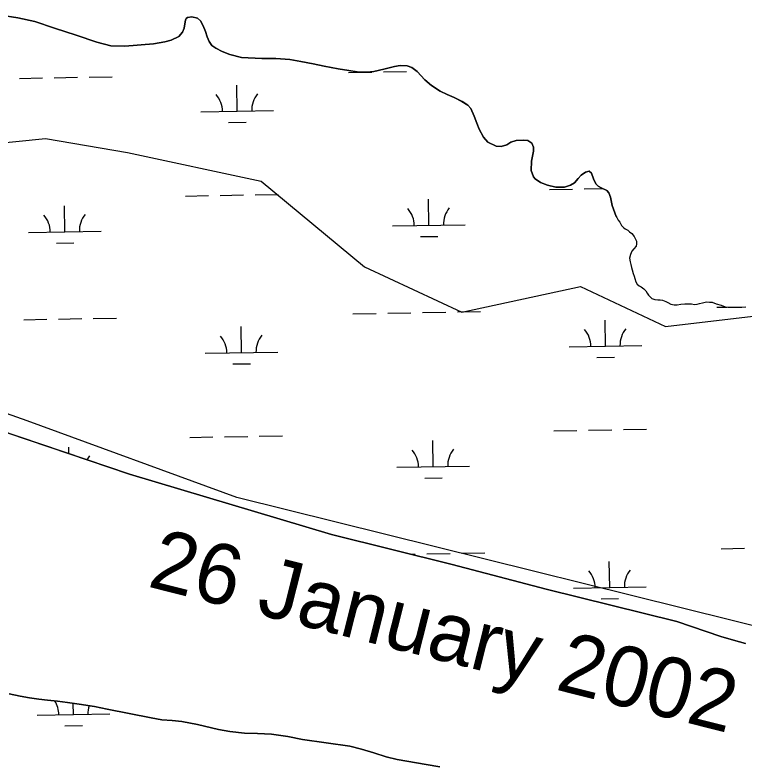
# Model space of a CAD drawing. Extents: x 3914892 to 3953151, y 242587 to 268572.
# Drawn here: x 3947793 to 3948799, y 254679 to 255715 of the extents above; entities that cross this region are included whole.
import ezdxf

# ---------------------------------------------------------------- set-up
doc = ezdxf.new("R2010")
doc.units = 0
for name, color, linetype in [('V-RIVR-IDEN', 7, 'Continuous'), ('V-SITE-VEGE', 7, 'Continuous'), ('V-TOPO-SHOR', 7, 'Continuous'), ('V-WETL-SWMP', 7, 'Continuous')]:
    doc.layers.add(name, color=color, linetype=linetype)

msp = doc.modelspace()

# ---------------------------------------------------------------- linework, layer by layer
at = {"layer": 'V-SITE-VEGE'}
for points in [[(3947679.8, 255529.4), (3947834.8, 255545.1), (3947947.9, 255525.5), (3948132.3, 255486.2), (3948274.7, 255368.3), (3948408.8, 255305.4), (3948572.2, 255340.8), (3948689.5, 255285.8), (3948857.1, 255305.4), (3948928.4, 255325.1), (3948999.6, 255356.5), (3949054.1, 255376.1), (3949066.6, 255376.1), (3949129.5, 255395.8), (3949163, 255340.8), (3949204.9, 255293.6), (3949288.7, 255258.3), (3949318, 255250.4), (3949401.8, 255297.5), (3949506.6, 255289.7), (3949552.7, 255266.1)], [(3949615.5, 254731.7), (3949368.3, 254751.3), (3948987, 254829.9), (3948098.8, 255050), (3947809.7, 255156.1), (3947520.6, 255258.3)]]:
    msp.add_lwpolyline(points, dxfattribs=at)
at = {"layer": 'V-TOPO-SHOR'}
for points in [[(3948621.7, 255437.5), (3948616.2, 255452.6), (3948613.6, 255464.2), (3948611.5, 255470), (3948608.5, 255473.4), (3948601, 255476.9), (3948596.7, 255479.1), (3948593.5, 255482.4), (3948590.4, 255489.4), (3948587.6, 255497.4), (3948584.4, 255499.8), (3948579.2, 255498.7), (3948573.4, 255494.6), (3948569.1, 255489.7), (3948563.9, 255484), (3948558.6, 255480.7), (3948550.2, 255478), (3948538.3, 255478), (3948526.8, 255480.8), (3948517.1, 255484.5), (3948509.8, 255489.4), (3948507.4, 255492.2), (3948504.6, 255501), (3948504.9, 255513.8), (3948507.7, 255527.3), (3948507.4, 255532.9), (3948505.5, 255538.7), (3948499.6, 255542.1), (3948493.2, 255542.8), (3948483.5, 255542.4), (3948476.4, 255539.9), (3948470.8, 255536.4), (3948463, 255534.1), (3948456, 255534.4), (3948444.6, 255539.8), (3948438.5, 255547), (3948432.9, 255557.7), (3948429.4, 255566.1), (3948426, 255575.7), (3948421.2, 255586.3), (3948417.2, 255590.8), (3948409.1, 255595.9), (3948398.1, 255601.4), (3948388.8, 255605.4), (3948378.9, 255610.1), (3948366.8, 255618), (3948358, 255625.9), (3948347.2, 255637.4), (3948339.7, 255642.9), (3948333.4, 255645), (3948323.8, 255645.4), (3948315.8, 255644.3), (3948301.4, 255640.3), (3948287.6, 255637.1), (3948277.9, 255636.5), (3948264.5, 255636.9), (3948252.8, 255638.5), (3948238.1, 255640.9), (3948219.2, 255644.5), (3948203.9, 255647.7), (3948186.9, 255651.2), (3948171.8, 255654), (3948152.3, 255655.1), (3948132.9, 255655.4), (3948105.1, 255656.4), (3948089.2, 255660.6), (3948078.5, 255665), (3948069.8, 255669.5), (3948064.3, 255673.3), (3948060.4, 255678.6), (3948057.5, 255685.2), (3948055.2, 255692.2), (3948052.1, 255700), (3948048.4, 255707.2), (3948044.5, 255710.7), (3948036.8, 255712.8), (3948030.8, 255711.5), (3948028.6, 255710.3), (3948027.9, 255708.1), (3948027.1, 255703), (3948025.8, 255697.2), (3948023.9, 255691.5), (3948018.6, 255685.6), (3948008.2, 255680.5), (3947999.2, 255678.1), (3947983.6, 255675.5), (3947944.1, 255672.3), (3947924.8, 255672.6), (3947905.8, 255677.9), (3947877, 255687.5), (3947847.3, 255696.9), (3947820.3, 255706.1), (3947796.9, 255711.2), (3947773.2, 255715.1)], [(3948621.7, 255437.5), (3948622.3, 255436.1), (3948624.5, 255432.3), (3948626.5, 255429.6), (3948629, 255425.1), (3948631.6, 255422.3), (3948634.1, 255420.4), (3948637.6, 255418.4), (3948640.1, 255416.3), (3948643, 255413.9), (3948646.3, 255409.9), (3948647.9, 255407.1), (3948649.7, 255403.3), (3948649.8, 255400), (3948648.9, 255396.8), (3948646.1, 255392.9), (3948643.3, 255389.6), (3948641.1, 255385.3), (3948640, 255379.9), (3948640.7, 255374.8), (3948641.7, 255371.4), (3948642.9, 255367.2), (3948643.8, 255363.9), (3948645, 255359), (3948646.2, 255355.2), (3948647.2, 255351.9), (3948648.8, 255347.6), (3948650.6, 255344), (3948653.1, 255342.1), (3948655.9, 255340.6), (3948659.5, 255337.8), (3948662.5, 255334.8), (3948664.2, 255332), (3948666, 255328.9), (3948668.2, 255326.7), (3948670.7, 255324.6), (3948674.9, 255323), (3948679, 255322.5), (3948682, 255322.7), (3948685.5, 255322.2), (3948689.9, 255320.4), (3948692.8, 255318.9), (3948696.9, 255316.7), (3948701.5, 255315.6), (3948705.5, 255315.7), (3948710.6, 255316.8), (3948716.4, 255317.1), (3948721.7, 255317.3), (3948725.2, 255317), (3948729.6, 255316.3), (3948733.2, 255316.6), (3948736.6, 255317.6), (3948740.5, 255318.6), (3948746, 255319.7), (3948750.2, 255319.6), (3948754, 255319.3), (3948759.6, 255317.3), (3948766.2, 255315.1), (3948771.8, 255312.9), (3948776, 255312.4), (3948781.3, 255312.3), (3948785, 255312.4), (3948790.3, 255312.5), (3948794.7, 255312.6), (3948800.5, 255312.9)], [(3947054, 255408.5), (3947327.2, 255301.4), (3947494.9, 255241.7), (3947755, 255148.5), (3947950.8, 255082.4), (3948229.1, 254999.4), (3948395.6, 254958.1), (3948525.2, 254923.7), (3948705.2, 254879.3)], [(3948705.2, 254879.3), (3948765.8, 254858.5), (3948783.4, 254853.7), (3948799.8, 254849)], [(3948073.2, 254730.3), (3948044.6, 254737.3), (3948022.7, 254741.5), (3948009.5, 254742.7), (3947995.1, 254743.7), (3947980.7, 254746.6), (3947919.9, 254758.7), (3947902.3, 254762.1), (3947881.2, 254765.4), (3947865.3, 254767.7), (3947851.6, 254769.5), (3947837.7, 254770.8), (3947825.9, 254772.5), (3947812.8, 254774), (3947799.8, 254776.4), (3947784.7, 254779.6)], [(3948378.6, 254678.9), (3948359.4, 254682.5), (3948319.5, 254689.1), (3948304.7, 254693), (3948287.3, 254698.3), (3948270.6, 254703.4), (3948254.5, 254707.5), (3948189.2, 254716.7), (3948168.9, 254720.7), (3948146.5, 254724.1), (3948127.2, 254725.2), (3948109.4, 254725.3), (3948088.8, 254727.8), (3948073.2, 254730.3)]]:
    msp.add_lwpolyline(points, dxfattribs=at)
at = {"layer": 'V-WETL-SWMP'}
for p, q in [((3947773.1, 255715.1), (3947796.9, 255711.2)), ((3947796.9, 255711.2), (3947820.3, 255706.1)), ((3948028.6, 255710.3), (3948030.8, 255711.5)), ((3948030.8, 255711.5), (3948036.8, 255712.8)), ((3948036.8, 255712.8), (3948044.5, 255710.7)), ((3948044.5, 255710.7), (3948048.4, 255707.2)), ((3947820.3, 255706.1), (3947847.3, 255696.9)), ((3948025.8, 255697.2), (3948027.1, 255703)), ((3948027.1, 255703), (3948027.9, 255708.1)), ((3948027.9, 255708.1), (3948028.6, 255710.3)), ((3948048.4, 255707.2), (3948052.1, 255700)), ((3947847.3, 255696.9), (3947877, 255687.5)), ((3948018.6, 255685.6), (3948023.9, 255691.5)), ((3948023.9, 255691.5), (3948025.8, 255697.2)), ((3948052.1, 255700), (3948055.2, 255692.2)), ((3948055.2, 255692.2), (3948057.5, 255685.2)), ((3947877, 255687.5), (3947905.8, 255677.9)), ((3947999.2, 255678.1), (3948008.2, 255680.5)), ((3948008.2, 255680.5), (3948018.6, 255685.6)), ((3948057.5, 255685.2), (3948060.4, 255678.6)), ((3947905.8, 255677.9), (3947924.8, 255672.6)), ((3947924.8, 255672.6), (3947944.1, 255672.3)), ((3947944.1, 255672.3), (3947983.6, 255675.5)), ((3947983.6, 255675.5), (3947999.2, 255678.1)), ((3948060.4, 255678.6), (3948064.3, 255673.3)), ((3948064.3, 255673.3), (3948069.8, 255669.5)), ((3948069.8, 255669.5), (3948078.5, 255665)), ((3948078.5, 255665), (3948089.2, 255660.6)), ((3948089.2, 255660.6), (3948105.1, 255656.4)), ((3948105.1, 255656.4), (3948132.9, 255655.4)), ((3948132.9, 255655.4), (3948152.3, 255655.1)), ((3948152.3, 255655.1), (3948171.8, 255654)), ((3948171.8, 255654), (3948186.9, 255651.2)), ((3948186.9, 255651.2), (3948203.9, 255647.7)), ((3948203.9, 255647.7), (3948219.2, 255644.5)), ((3948219.2, 255644.5), (3948238.1, 255640.9)), ((3948238.1, 255640.9), (3948252.8, 255638.5)), ((3948252.8, 255638.5), (3948264.5, 255636.9)), ((3948287.6, 255637.1), (3948301.4, 255640.3)), ((3948301.4, 255640.3), (3948315.8, 255644.3)), ((3948315.8, 255644.3), (3948323.8, 255645.4)), ((3948323.8, 255645.4), (3948333.4, 255645)), ((3948333.4, 255645), (3948339.7, 255642.9)), ((3948339.7, 255642.9), (3948347.2, 255637.4)), ((3947798.9, 255627.8), (3947830.9, 255628.4)), ((3947846.9, 255628.7), (3947878.9, 255629.3)), ((3947894.9, 255629.6), (3947926.8, 255630.1)), ((3948252.7, 255636), (3948284.7, 255636.5)), ((3948264.5, 255636.9), (3948277.9, 255636.5)), ((3948277.9, 255636.5), (3948287.6, 255637.1)), ((3948300.7, 255636.8), (3948332.7, 255637.4)), ((3948347.2, 255637.4), (3948358, 255625.9)), ((3948099, 255582.5), (3948098.4, 255618.5)), ((3948358, 255625.9), (3948366.8, 255618)), ((3948366.8, 255618), (3948378.9, 255610.1)), ((3948378.9, 255610.1), (3948388.8, 255605.4)), ((3948388.8, 255605.4), (3948398.1, 255601.4)), ((3948398.1, 255601.4), (3948409, 255595.9)), ((3948409, 255595.9), (3948417.2, 255590.8)), ((3948417.2, 255590.8), (3948421.2, 255586.3)), ((3948421.2, 255586.3), (3948426, 255575.7)), ((3948049.1, 255581.6), (3948149, 255583.4)), ((3948087.3, 255566.8), (3948111.3, 255567.3)), ((3948426, 255575.7), (3948429.4, 255566.1)), ((3948429.4, 255566.1), (3948432.9, 255557.7)), ((3948432.9, 255557.7), (3948438.5, 255547)), ((3948438.5, 255547), (3948444.6, 255539.8)), ((3948444.6, 255539.8), (3948456, 255534.4)), ((3948456, 255534.4), (3948463, 255534.1)), ((3948463, 255534.1), (3948470.8, 255536.4)), ((3948470.8, 255536.4), (3948476.4, 255539.9)), ((3948476.4, 255539.9), (3948483.5, 255542.4)), ((3948483.5, 255542.4), (3948493.2, 255542.8)), ((3948493.2, 255542.8), (3948499.6, 255542.1)), ((3948499.6, 255542.1), (3948505.5, 255538.7)), ((3948505.5, 255538.7), (3948507.4, 255532.9)), ((3948507.7, 255527.3), (3948504.9, 255513.8)), ((3948507.4, 255532.9), (3948507.7, 255527.3)), ((3948504.9, 255513.8), (3948504.6, 255501)), ((3948504.6, 255501), (3948507.4, 255492.2)), ((3948569.1, 255489.7), (3948573.4, 255494.6)), ((3948573.4, 255494.6), (3948579.2, 255498.7)), ((3948579.2, 255498.7), (3948584.4, 255499.8)), ((3948584.4, 255499.8), (3948587.6, 255497.4)), ((3948587.6, 255497.4), (3948590.4, 255489.4)), ((3948507.4, 255492.2), (3948509.8, 255489.4)), ((3948509.8, 255489.4), (3948517.1, 255484.5)), ((3948517.1, 255484.5), (3948526.8, 255480.8)), ((3948558.6, 255480.7), (3948563.9, 255484)), ((3948563.9, 255484), (3948569.1, 255489.7)), ((3948590.4, 255489.4), (3948593.5, 255482.4)), ((3948526.8, 255480.8), (3948538.3, 255478)), ((3948529.5, 255474.7), (3948561.5, 255475.3)), ((3948538.3, 255478), (3948550.2, 255478)), ((3948550.2, 255478), (3948558.6, 255480.7)), ((3948577.5, 255475.6), (3948602.9, 255476)), ((3948593.5, 255482.4), (3948596.7, 255479.1)), ((3948596.7, 255479.1), (3948601, 255476.9)), ((3948601, 255476.9), (3948608.5, 255473.4)), ((3948608.5, 255473.4), (3948611.5, 255470)), ((3948027.7, 255465.7), (3948059.7, 255466.3)), ((3948075.7, 255466.6), (3948107.7, 255467.2)), ((3948123.7, 255467.5), (3948155.7, 255468)), ((3948611.5, 255470), (3948613.6, 255464.2)), ((3948613.6, 255464.2), (3948616.2, 255452.6)), ((3947861.5, 255416.3), (3947860.9, 255452.3)), ((3948363.3, 255425.3), (3948362.7, 255461.3)), ((3948616.2, 255452.6), (3948621.7, 255437.5)), ((3948621.7, 255437.5), (3948622.3, 255436.1)), ((3948622.3, 255436.1), (3948624.5, 255432.3)), ((3948624.5, 255432.3), (3948626.5, 255429.6)), ((3948313.3, 255424.4), (3948413.3, 255426.2)), ((3948626.5, 255429.6), (3948629, 255425.1)), ((3948629, 255425.1), (3948631.6, 255422.3)), ((3948631.6, 255422.3), (3948634.1, 255420.4)), ((3948634.1, 255420.4), (3948637.6, 255418.4)), ((3947811.5, 255415.4), (3947911.5, 255417.2)), ((3948351.6, 255409.7), (3948375.6, 255410.1)), ((3948637.6, 255418.4), (3948640.1, 255416.3)), ((3948640.1, 255416.3), (3948643, 255413.9)), ((3948643, 255413.9), (3948646.3, 255409.9)), ((3947849.8, 255400.7), (3947873.8, 255401.1)), ((3948646.3, 255409.9), (3948647.9, 255407.1)), ((3948647.9, 255407.1), (3948649.7, 255403.3)), ((3948649.8, 255400), (3948648.9, 255396.8)), ((3948649.7, 255403.3), (3948649.8, 255400)), ((3948643.3, 255389.6), (3948641.1, 255385.3)), ((3948646.1, 255392.9), (3948643.3, 255389.6)), ((3948648.9, 255396.8), (3948646.1, 255392.9)), ((3948641.1, 255385.3), (3948640, 255379.9)), ((3948640, 255379.9), (3948640.7, 255374.8)), ((3948640.7, 255374.8), (3948641.7, 255371.4)), ((3948641.7, 255371.4), (3948642.9, 255367.2)), ((3948642.9, 255367.2), (3948643.8, 255363.9)), ((3948643.8, 255363.9), (3948645, 255359)), ((3948645, 255359), (3948646.2, 255355.2)), ((3948646.2, 255355.2), (3948647.2, 255351.9)), ((3948647.2, 255351.9), (3948648.8, 255347.6)), ((3948648.8, 255347.6), (3948650.6, 255344)), ((3948650.6, 255344), (3948653.1, 255342.1)), ((3948653.1, 255342.1), (3948655.9, 255340.6)), ((3948655.9, 255340.6), (3948659.5, 255337.8)), ((3948659.5, 255337.8), (3948662.5, 255334.8)), ((3948662.5, 255334.8), (3948664.2, 255332)), ((3948664.2, 255332), (3948666, 255328.9)), ((3948666, 255328.9), (3948668.2, 255326.7)), ((3948668.2, 255326.7), (3948670.7, 255324.6)), ((3948670.7, 255324.6), (3948674.9, 255323)), ((3948674.9, 255323), (3948679, 255322.5)), ((3948679, 255322.5), (3948682, 255322.7)), ((3948682, 255322.7), (3948685.5, 255322.2)), ((3948685.5, 255322.2), (3948689.9, 255320.4)), ((3948689.9, 255320.4), (3948692.8, 255318.9)), ((3948692.8, 255318.9), (3948696.9, 255316.7)), ((3948705.5, 255315.7), (3948710.6, 255316.8)), ((3948710.6, 255316.8), (3948716.4, 255317.1)), ((3948716.4, 255317.1), (3948721.7, 255317.3)), ((3948721.7, 255317.3), (3948725.2, 255317)), ((3948725.2, 255317), (3948729.6, 255316.3)), ((3948733.2, 255316.6), (3948736.6, 255317.6)), ((3948736.6, 255317.6), (3948740.5, 255318.6)), ((3948740.5, 255318.6), (3948746, 255319.7)), ((3948746, 255319.7), (3948750.2, 255319.6)), ((3948750.2, 255319.6), (3948754, 255319.3)), ((3948754, 255319.3), (3948759.6, 255317.3)), ((3948759.6, 255317.3), (3948766.2, 255315.1)), ((3948402.6, 255305.9), (3948434.6, 255306.5)), ((3948696.9, 255316.7), (3948701.5, 255315.6)), ((3948701.5, 255315.6), (3948705.5, 255315.7)), ((3948729.6, 255316.3), (3948733.2, 255316.6)), ((3948760.5, 255312.3), (3948774.6, 255312.6)), ((3948766.2, 255315.1), (3948771.8, 255312.9)), ((3948771.8, 255312.9), (3948776, 255312.4)), ((3948776, 255312.4), (3948781.3, 255312.3)), ((3948781.3, 255312.3), (3948785, 255312.4)), ((3948785, 255312.4), (3948790.3, 255312.5)), ((3948790.3, 255312.5), (3948794.7, 255312.6)), ((3948794.7, 255312.6), (3948800.5, 255312.9)), ((3947852.8, 255296.1), (3947884.8, 255296.7)), ((3947900.8, 255296.9), (3947932.8, 255297.5)), ((3948258.7, 255303.3), (3948290.6, 255303.9)), ((3948306.6, 255304.2), (3948338.6, 255304.8)), ((3948354.6, 255305.1), (3948386.6, 255305.6)), ((3947804.8, 255295.2), (3947836.8, 255295.8)), ((3948105, 255249.8), (3948104.4, 255285.8)), ((3948606.8, 255258.8), (3948606.2, 255294.8)), ((3948556.8, 255257.9), (3948656.8, 255259.7)), ((3948055, 255248.9), (3948155, 255250.7)), ((3948093.3, 255234.2), (3948117.3, 255234.6)), ((3948595.1, 255243.2), (3948619.1, 255243.6)), ((3947950.8, 255082.4), (3947755, 255148.5)), ((3948535.5, 255142.1), (3948567.5, 255142.7)), ((3948583.5, 255143), (3948615.5, 255143.5)), ((3948631.5, 255143.8), (3948663.5, 255144.4)), ((3948033.7, 255133.1), (3948065.7, 255133.7)), ((3948081.7, 255134), (3948113.6, 255134.5)), ((3948129.6, 255134.8), (3948161.6, 255135.4)), ((3948369.3, 255092.7), (3948368.6, 255128.7)), ((3947867, 255110.7), (3947866.8, 255119.7)), ((3948319.3, 255091.8), (3948419.3, 255093.6)), ((3948229.1, 254999.4), (3947950.8, 255082.4)), ((3948357.6, 255077), (3948381.6, 255077.5)), ((3948395.6, 254958.1), (3948229.1, 254999.4)), ((3948766.4, 254979.7), (3948798.4, 254980.3)), ((3948339.4, 254972.1), (3948344.6, 254972.2)), ((3948360.6, 254972.4), (3948392.6, 254973)), ((3948408.6, 254973.3), (3948440.6, 254973.9)), ((3948525.2, 254923.7), (3948395.6, 254958.1)), ((3948612.8, 254926.2), (3948612.1, 254962.2)), ((3948705.2, 254879.3), (3948525.2, 254923.7)), ((3948562.8, 254925.3), (3948662.8, 254927.1)), ((3948601.1, 254910.6), (3948625, 254911)), ((3948765.8, 254858.5), (3948705.2, 254879.3)), ((3948783.4, 254853.7), (3948765.8, 254858.5)), ((3948799.8, 254849), (3948783.4, 254853.7)), ((3947784.7, 254779.6), (3947799.8, 254776.4)), ((3947799.8, 254776.4), (3947812.8, 254774)), ((3947812.8, 254774), (3947825.9, 254772.5)), ((3947825.9, 254772.5), (3947837.7, 254770.8)), ((3947837.7, 254770.8), (3947851.6, 254769.5)), ((3947851.6, 254769.5), (3947865.3, 254767.7)), ((3947865.3, 254767.7), (3947881.2, 254765.4)), ((3947873.4, 254751.1), (3947873.1, 254766.5)), ((3947881.2, 254765.4), (3947902.3, 254762.1)), ((3947902.3, 254762.1), (3947919.9, 254758.7)), ((3947919.9, 254758.7), (3947980.7, 254746.6)), ((3947823.4, 254750.2), (3947923.4, 254752)), ((3947980.7, 254746.6), (3947995.1, 254743.7)), ((3947995.1, 254743.7), (3948009.5, 254742.7)), ((3948009.5, 254742.7), (3948022.7, 254741.5)), ((3948022.7, 254741.5), (3948044.6, 254737.3)), ((3948044.6, 254737.3), (3948073.2, 254730.3)), ((3947861.7, 254735.4), (3947885.7, 254735.9)), ((3948073.2, 254730.3), (3948088.8, 254727.8)), ((3948088.8, 254727.8), (3948109.4, 254725.3)), ((3948109.4, 254725.3), (3948127.2, 254725.2)), ((3948127.2, 254725.2), (3948146.5, 254724.1)), ((3948146.5, 254724.1), (3948168.9, 254720.7)), ((3948168.9, 254720.7), (3948189.2, 254716.7)), ((3948189.2, 254716.7), (3948254.5, 254707.5)), ((3948254.5, 254707.5), (3948270.6, 254703.4)), ((3948270.6, 254703.4), (3948287.3, 254698.3)), ((3948287.3, 254698.3), (3948304.7, 254693)), ((3948304.7, 254693), (3948319.5, 254689.1)), ((3948319.5, 254689.1), (3948359.4, 254682.5)), ((3948359.4, 254682.5), (3948378.6, 254678.9))]:
    msp.add_line(p, q, dxfattribs=at)
for centre, start, end in [((3948043.8, 255582), 0.2532, 41.7968), ((3948154.3, 255583.9), 140.2532, 181.7968), ((3948308.1, 255424.8), 0.2532, 41.7968), ((3948418.6, 255426.8), 140.2532, 181.7968), ((3947806.3, 255415.8), 0.2532, 41.7968), ((3947916.7, 255417.8), 140.2532, 181.7968), ((3948551.6, 255258.3), 0.2532, 41.7968), ((3948662, 255260.3), 140.2532, 181.7968), ((3948049.8, 255249.3), 0.2532, 41.7968), ((3948160.2, 255251.3), 140.2532, 181.7968), ((3948314, 255092.2), 0.2532, 41.7968), ((3948424.5, 255094.1), 140.2532, 181.7968), ((3947922.7, 255085.2), 140.2532, 150.8917), ((3948557.5, 254925.7), 0.2532, 41.7968), ((3948668, 254927.7), 140.2532, 181.7968), ((3947818.2, 254750.6), 0.2532, 33.1986), ((3947928.6, 254752.5), 162.4209, 181.7968)]:
    msp.add_arc(centre, 35.2, start, end, dxfattribs=at)

# ---------------------------------------------------------------- texts
at = {"layer": 'V-RIVR-IDEN'}
msp.add_text('26 January 2002', height=83, rotation=345.8356, dxfattribs=at).set_placement((3947973.9, 254927.9))

doc.saveas('drawing.dxf')
